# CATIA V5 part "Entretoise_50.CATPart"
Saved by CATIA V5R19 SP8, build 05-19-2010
Part number: Entretoise_50
Bounding box of the stored display mesh (mm): x -19 to 19, y -18.807 to 18.807, z 0 to 50
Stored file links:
  G:\EU_thinkMotion\CFAO_2010\MMS_groupe1\MMS_groupe1\OK\vduret\vduret\CATIA\Entretoise_50.CATPart
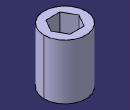
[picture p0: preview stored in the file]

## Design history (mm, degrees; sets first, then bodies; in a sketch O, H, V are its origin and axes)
Body1 (main body)
  Sketch1 on xy-plane, origin (0, 0, 0), H (1, 0, 0), V (0, 1, 0)
    circle A1 centre (0, 0) radius 19
    point P1 (0, 0)
    point P2 (6.3509, -11)
    point P3 (12.7017, 0)
    point P4 (6.3509, 11)
    point P5 (-6.3509, 11)
    point P6 (-12.7017, 0)
    point P7 (-6.3509, -11)
    point P8 (9.5263, -5.5)
    line L1 (6.3509, -11) -> (12.7017, 0)
    line L2 (12.7017, 0) -> (6.3509, 11)
    line L3 (6.3509, 11) -> (-6.3509, 11)
    line L4 (-6.3509, 11) -> (-12.7017, 0)
    line L5 (-12.7017, 0) -> (-6.3509, -11)
    line L6 (-6.3509, -11) -> (6.3509, -11)
    construction line L7 (0, 0) -> (9.5263, -5.5)
    construction circle A2 centre (0, 0) radius 12.7017
    construction arc A3 centre (-12.7017, 0) radius 12.7017 from (-6.3509, 11) to (-6.3509, -11) cw
    construction arc A4 centre (12.7017, 0) radius 12.7017 from (6.3509, 11) to (6.3509, -11) ccw
    radius A1 = 19
    distance L3 L6 = 22
    coincidence: A2 P2, A2 P3, A2 P4, A2 P5, A2 P6, A2 P7, A3 P1, A4 P1, P1 O
    midpoint: P8 L1
    parallelism: L1 L4
    horizontal: L3 H
  Pad1: profile Sketch1, direction (0, 0, 1), length 50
